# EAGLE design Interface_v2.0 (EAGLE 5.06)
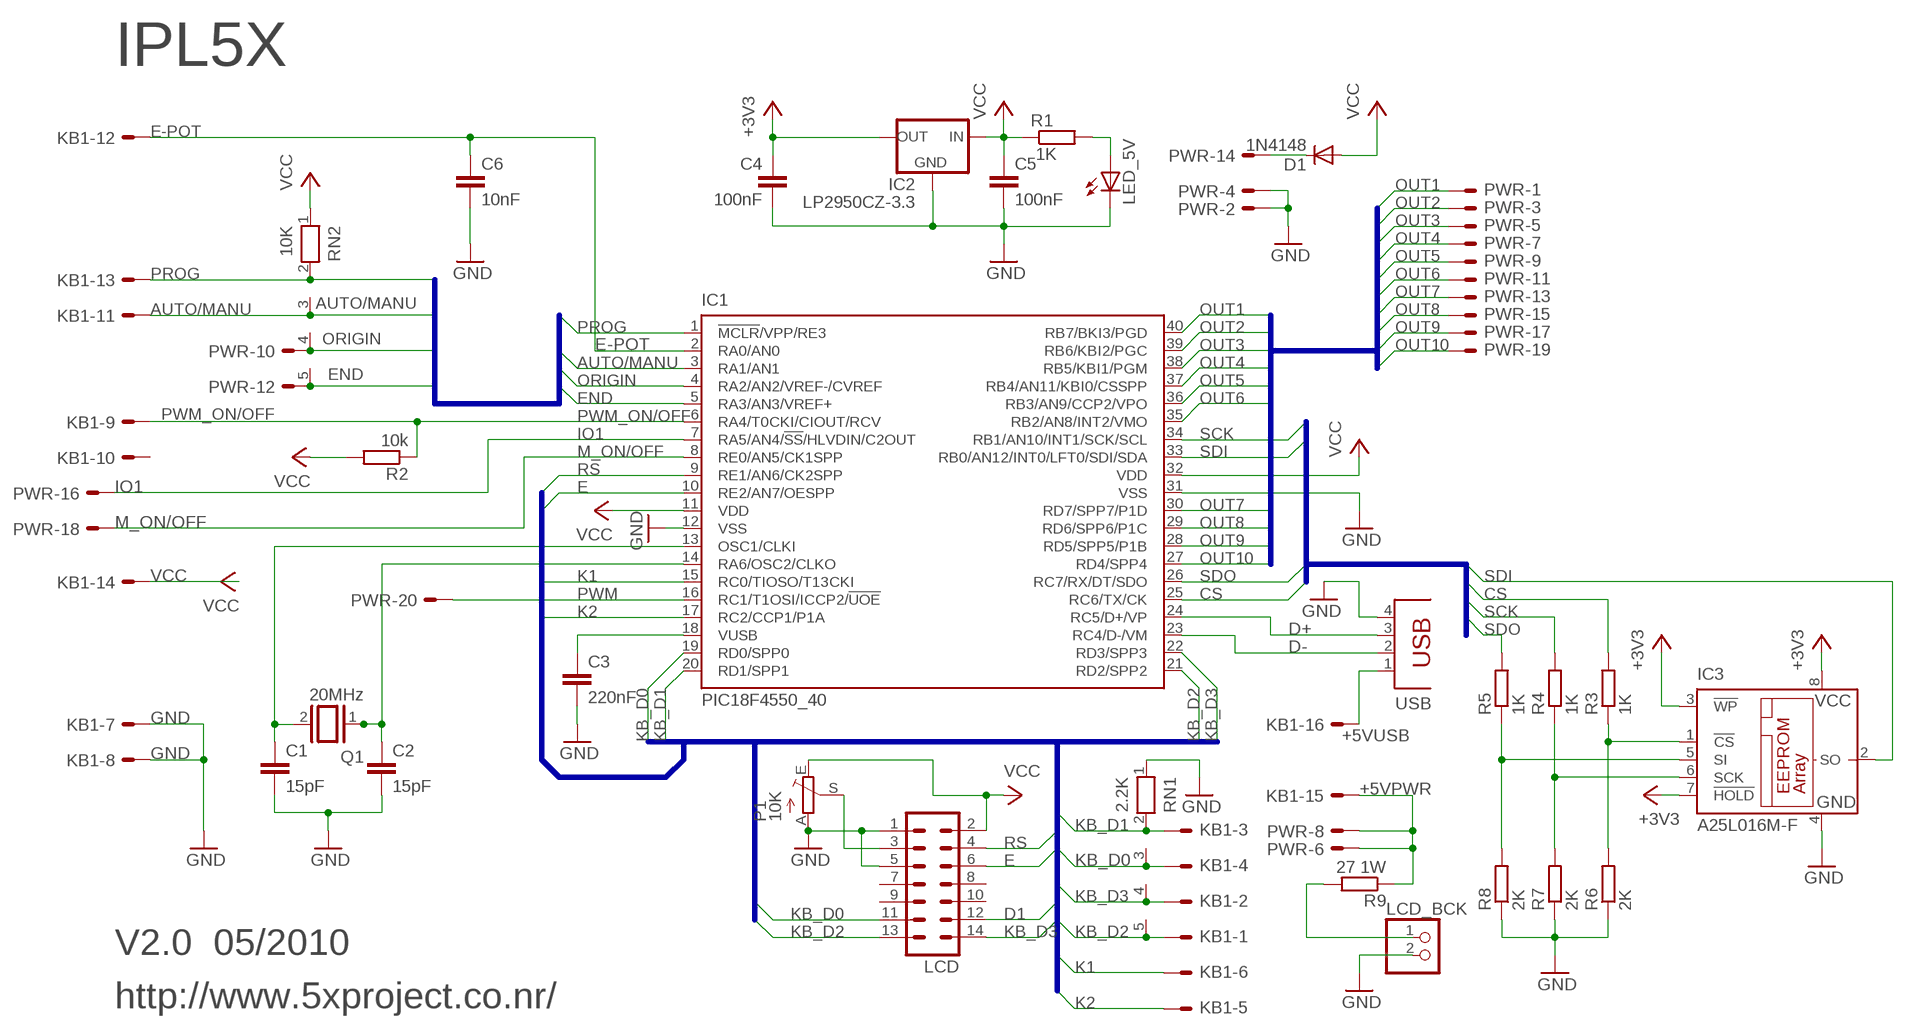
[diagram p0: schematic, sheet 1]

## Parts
C1  15pF  C-EU025-024X044  [C025-024X044]
C2  15pF  C-EU025-024X044  [C025-024X044]
C3  220nF  C-EU050-030X075  [C050-030X075]
C4  100nF  C-EU050-035X075  [C050-035X075]
C5  100nF  C-EU050-030X075  [C050-030X075]
C6  10nF  C-EU050-030X075  [C050-030X075]
D1  1N4148  1N4148DO35-10  [DO35-10]
IC1  PIC18F4550_40  [DIL40]
IC2  LP2950CZ-3.3  LP2950ACZ-3.3  [TO92]
IC3  A25L016M-F  25LC080SN  [SO-08]
KB1  ML16LE  [ML16L]
LCD  ML14L  [ML14L]
LCD_BCK  PINHD-1X2  [1X02]
LED_5V  LED5MM  [LED5MM]
P1  10K  TRIM_EU-LI10  [LI10]
PWR  ML203M20LE  [3M_20L]
Q1  20MHz  XTAL/S  [QS]
R1  1K  R-EU_0207/10  [0207/10]
R2  10k  R-EU_0207/10  [0207/10]
R3  1K  R-EU_0207/10  [0207/10]
R4  1K  R-EU_0207/10  [0207/10]
R5  1K  R-EU_0207/10  [0207/10]
R6  2K  R-EU_0204/7  [0204/7]
R7  2K  R-EU_0204/7  [0204/7]
R8  2K  R-EU_0204/7  [0204/7]
R9  27 1W  R-EU_0309/12  [0309/12]
RN1  2.2K  RN04  [RN-5]
RN2  10K  RN04  [RN-5]
USB  PN61729  [PN61729]

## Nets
+3V3: C4.1 IC2.1(OUT) IC3.3(!WP) IC3.7(!HOLD) IC3.8(VCC)
+5VPWR: KB1.15 PWR.6 PWR.8 R9.1
+5VUSB: KB1.16 USB.1
AUTO/MANU: IC1.3(RA1/AN1) KB1.11 RN2.3
CS: IC1.25(RC6/TX/CK) R3.2
D1: LCD.12
D+: IC1.24(RC5/D+/VP) USB.3
D-: IC1.23(RC4/D-/VM) USB.2
E: IC1.10(RE2/AN7/OESPP) LCD.6
E-POT: C6.1 IC1.2(RA0/AN0) KB1.12
END: IC1.5(RA3/AN3/VREF+) PWR.12 RN2.5
GND: C1.2 C2.2 C3.2 C4.2 C5.2 C6.2 IC1.12(VSS) IC1.31(VSS) IC2.2(GND) IC3.4(GND) KB1.7 KB1.8 LCD.1 LCD.5 LCD_BCK.2 LED_5V.K(C) P1.A PWR.2 PWR.4 R6.1 R7.1 R8.1 RN1.1 USB.4
IO1: IC1.7(RA5/AN4/!SS!/HLVDIN/C2OUT) PWR.16
K1: IC1.15(RC0/TIOSO/T13CKI) KB1.6
K2: IC1.17(RC2/CCP1/P1A) KB1.5
KB_D0: IC1.19(RD0/SPP0) KB1.4 LCD.11 RN1.3
KB_D1: IC1.20(RD1/SPP1) KB1.3 RN1.2
KB_D2: IC1.21(RD2/SPP2) KB1.1 LCD.13 RN1.5
KB_D3: IC1.22(RD3/SPP3) KB1.2 LCD.14 RN1.4
M_ON/OFF: IC1.8(RE0/AN5/CK1SPP) PWR.18
N$1: C2.1 IC1.14(RA6/OSC2/CLKO) Q1.1
N$2: C1.1 IC1.13(OSC1/CLKI) Q1.2
N$6: LED_5V.A R1.2
N$7: C3.1 IC1.18(VUSB)
N$8: IC3.1(!CS) R3.1 R6.2
N$10: IC3.6(SCK) R4.1 R7.2
N$12: LCD_BCK.1 R9.2
N$14: IC3.5(SI) R5.1 R8.2
N$16: LCD.3 P1.S
N$51: D1.C PWR.14
ORIGIN: IC1.4(RA2/AN2/VREF-/CVREF) PWR.10 RN2.4
OUT1: IC1.40(RB7/BKI3/PGD) PWR.1
OUT2: IC1.39(RB6/KBI2/PGC) PWR.3
OUT3: IC1.38(RB5/KBI1/PGM) PWR.5
OUT4: IC1.37(RB4/AN11/KBI0/CSSPP) PWR.7
OUT5: IC1.36(RB3/AN9/CCP2/VPO) PWR.9
OUT6: IC1.35(RB2/AN8/INT2/VMO) PWR.11
OUT7: IC1.30(RD7/SPP7/P1D) PWR.13
OUT8: IC1.29(RD6/SPP6/P1C) PWR.15
OUT9: IC1.28(RD5/SPP5/P1B) PWR.17
OUT10: IC1.27(RD4/SPP4) PWR.19
PROG: IC1.1(!MCLR!/VPP/RE3) KB1.13 RN2.2
PWM: IC1.16(RC1/T1OSI/ICCP2/!UOE) PWR.20
PWM_ON/OFF: IC1.6(RA4/T0CKI/CIOUT/RCV) KB1.9 R2.1
RS: IC1.9(RE1/AN6/CK2SPP) LCD.4
SCK: IC1.34(RB1/AN10/INT1/SCK/SCL) R4.2
SDI: IC1.33(RB0/AN12/INT0/LFT0/SDI/SDA) IC3.2(SO)
SDO: IC1.26(RC7/RX/DT/SDO) R5.2
VCC: C5.1 D1.A IC1.11(VDD) IC1.32(VDD) IC2.3(IN) KB1.14 LCD.2 P1.E R1.1 R2.2 RN2.1
Unconnected: KB1.10 LCD.7 LCD.8 LCD.9 LCD.10

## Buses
OUT1,OUT2,OUT3,OUT4,OUT5,OUT6,OUT7,OUT8,OUT9,OUT10
SDI,SDO,SCK,CS
PROG,AUTO/MANU,ORIGIN,END,M_ON/OFF
D0,D1,D2,D3,E,RS,K1,K2

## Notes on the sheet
- IPL5X
- V2.0  05/2010
- http://www.5xproject.co.nr/

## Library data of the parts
C1-C6 = rcl:C-EU: CAPACITOR, European symbol
D1 = diode:1N4148: DIODE
IC1 = microchip:PIC18F4*_40: USB Microcontrollers with nanoWatt Technology High-Performance, Enhanced Flash, 28/40/44-Pin, Source: http://ww1.microchip.com/downloads/en/devicedoc/39632c.pdf
IC2 = v-reg:LP2950?*: Source: http://cache.national.com/ds/LP/LP2950.pdf
IC3 = microchip:25*: Serial EEPROM 4 K, SPI bus
KB1 = con-harting-ml:ML16?E: HARTING
LCD = con-harting-ml:ML14: HARTING
LCD_BCK = pinhead:PINHD-1X2: PIN HEADER
LED_5V = led:LED: LED
P1 = pot:TRIM_EU-: POTENTIOMETER
PWR = con-harting-ml:ML20?E: HARTING
Q1 = special:XTAL/S: CRYSTAL
R1-R9 = rcl:R-EU_: RESISTOR, European symbol
RN1 RN2 = resistor-net:RN04: RESISTOR NETWORK
USB = con-berg:PN61729: BERG USB connector

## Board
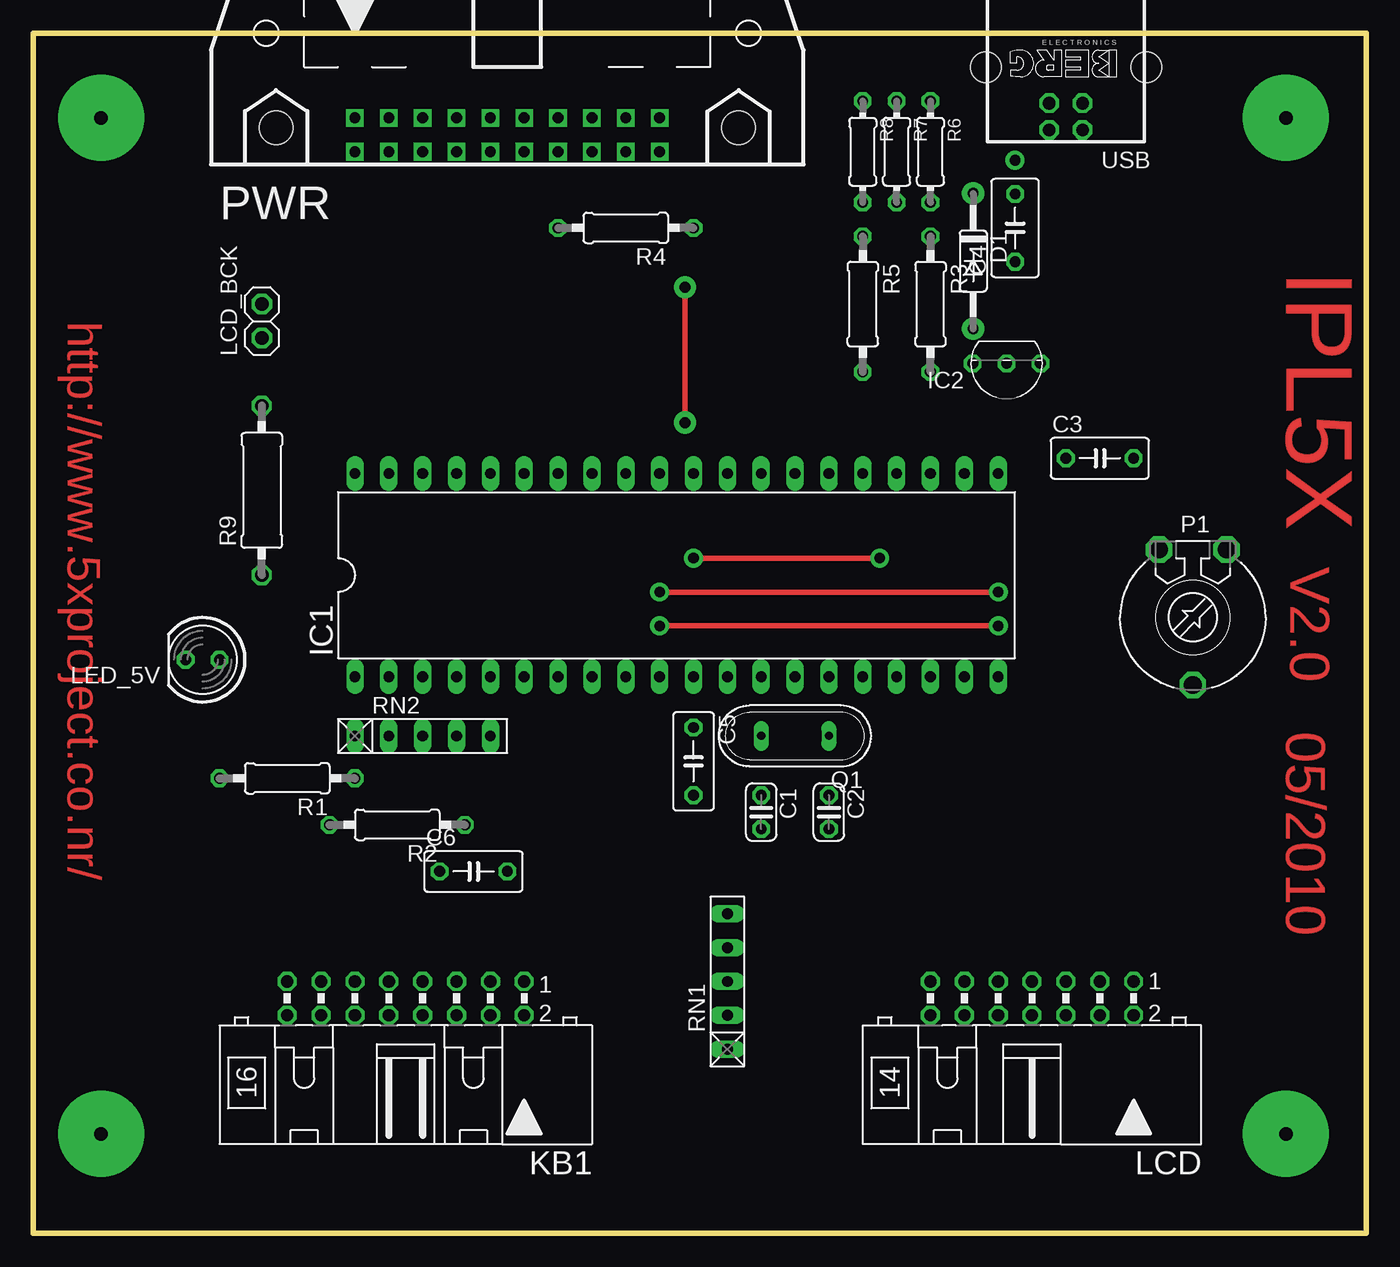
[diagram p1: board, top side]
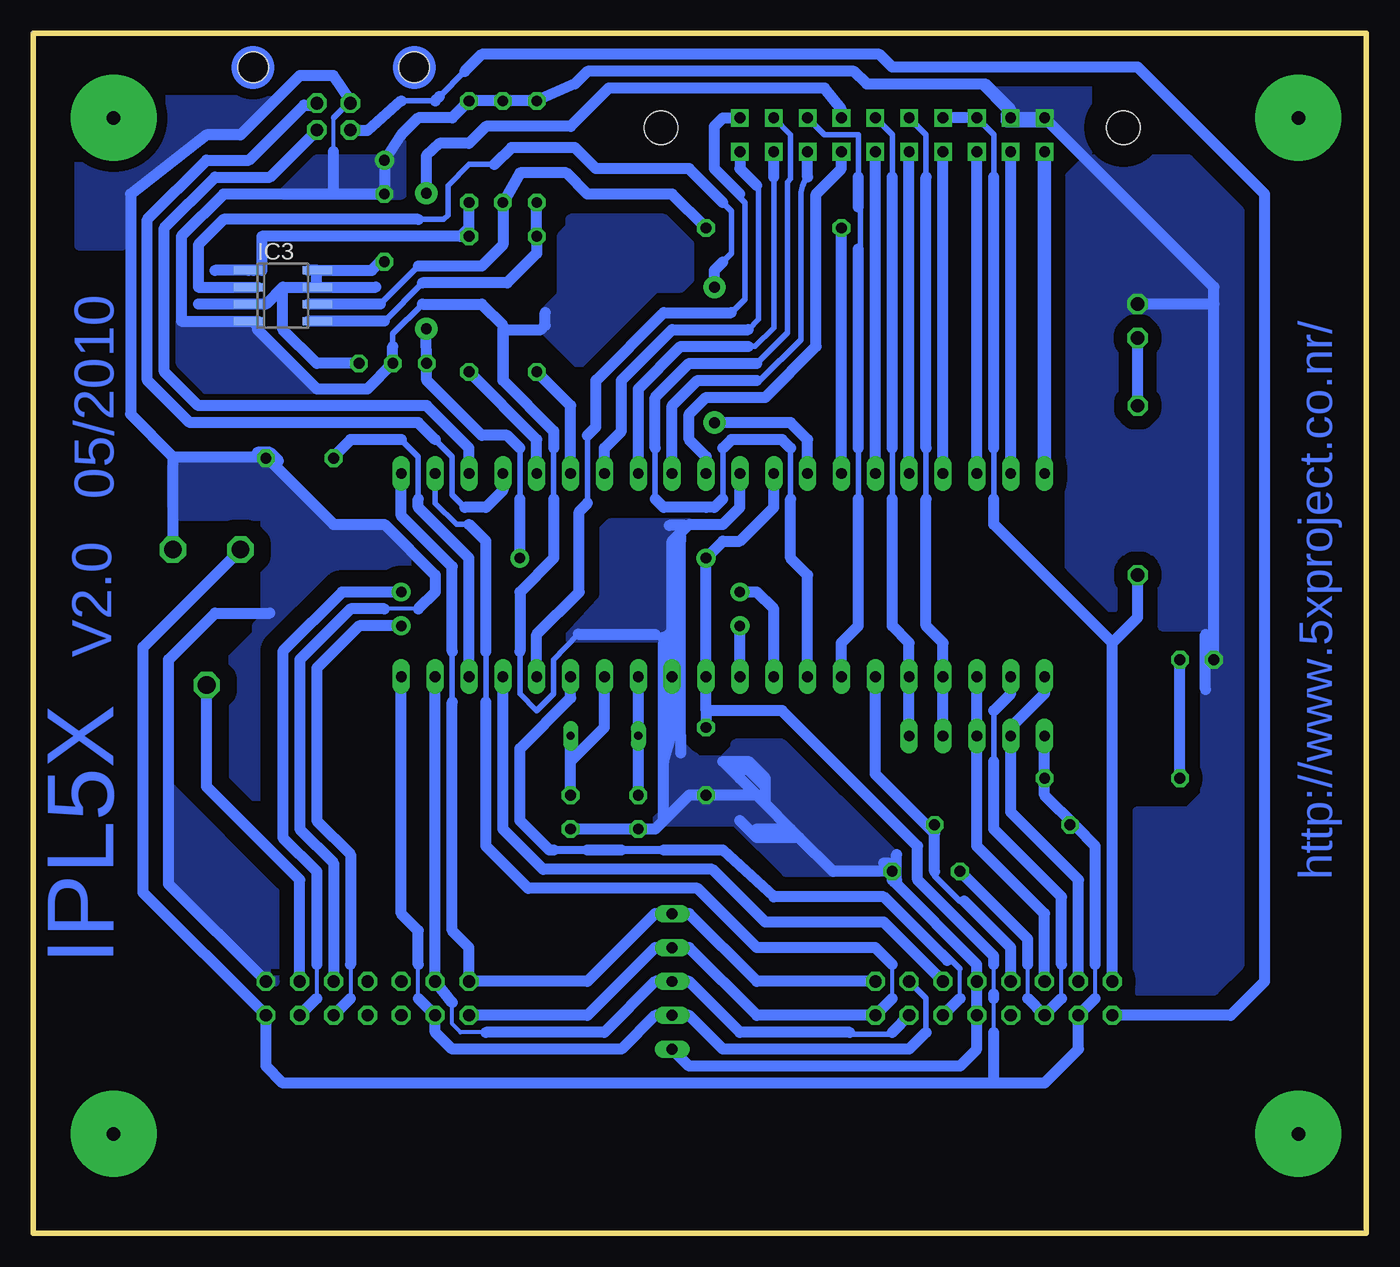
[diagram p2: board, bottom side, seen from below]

Size 100 x 90 mm. Coordinates in mm from the lower left corner, seen from the top.
Outline: 0,0 100,0 100,90 0,90 0,0
Copper layers (1*16): Top 0.035mm / dielectric 1.5mm / Bottom 0.035mm
Design rules "default *": minimum track width 10mil, minimum drill 24mil, track to track 15mil, track to pad 15mil, pad to pad 15mil, via to via 15mil, smd to smd 8mil, copper to edge 40mil, drill to drill 8mil, minimum pad ring 10mil, minimum via ring 8mil, stop-mask expansion 4mil, vias tented up to drill 0mil, thermal gap 10mil

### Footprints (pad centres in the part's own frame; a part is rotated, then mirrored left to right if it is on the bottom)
C025-024X044 = drill 0.813 octagon: 1 -1.27,0; 2 1.27,0
C050-030X075 = drill 0.813 octagon: 1 -2.54,0; 2 2.54,0
C050-035X075 = drill 0.813 octagon: 1 -2.54,0; 2 2.54,0
DO35-10 = drill 0.813 pad 1.676 round: A 5.08,0; C -5.08,0
DIL40 = drill 0.813 long: 1 -24.13,-7.62; 2 -21.59,-7.62; 3 -19.05,-7.62; 4 -16.51,-7.62; 5 -13.97,-7.62; 6 -11.43,-7.62; 7 -8.89,-7.62; 8 -6.35,-7.62; 9 -3.81,-7.62; 10 -1.27,-7.62; 11 1.27,-7.62; 12 3.81,-7.62; 13 6.35,-7.62; 14 8.89,-7.62; 15 11.43,-7.62; 16 13.97,-7.62; 17 16.51,-7.62; 18 19.05,-7.62; 19 21.59,-7.62; 20 24.13,-7.62; 21 24.13,7.62; 22 21.59,7.62; 23 19.05,7.62; 24 16.51,7.62; 25 13.97,7.62; 26 11.43,7.62; 27 8.89,7.62; 28 6.35,7.62; 29 3.81,7.62; 30 1.27,7.62; 31 -1.27,7.62; 32 -3.81,7.62; 33 -6.35,7.62; 34 -8.89,7.62; 35 -11.43,7.62; 36 -13.97,7.62; 37 -16.51,7.62; 38 -19.05,7.62; 39 -21.59,7.62; 40 -24.13,7.62
TO92 = drill 0.813 octagon: 1 -2.54,0; 2 0,0; 3 2.54,0
SO-08 = smd 0.6 x 2.2: 1 -1.905,-2.6; 2 -0.635,-2.6; 3 0.635,-2.6; 4 1.905,-2.6; 5 1.905,2.6; 6 0.635,2.6; 7 -0.635,2.6; 8 -1.905,2.6
ML16L = drill 0.914 octagon: 1 -8.89,-1.27; 2 -8.89,1.27; 3 -6.35,-1.27; 4 -6.35,1.27; 5 -3.81,-1.27; 6 -3.81,1.27; 7 -1.27,-1.27; 8 -1.27,1.27; 9 1.27,-1.27; 10 1.27,1.27; 11 3.81,-1.27; 12 3.81,1.27; 13 6.35,-1.27; 14 6.35,1.27; 15 8.89,-1.27; 16 8.89,1.27
ML14L = drill 0.914 octagon: 1 -7.62,-1.27; 2 -7.62,1.27; 3 -5.08,-1.27; 4 -5.08,1.27; 5 -2.54,-1.27; 6 -2.54,1.27; 7 0,-1.27; 8 0,1.27; 9 2.54,-1.27; 10 2.54,1.27; 11 5.08,-1.27; 12 5.08,1.27; 13 7.62,-1.27; 14 7.62,1.27
1X02 = drill 1.016 octagon: 1 -1.27,0; 2 1.27,0
LED5MM = drill 0.813 octagon: A -1.27,0; K 1.27,0
LI10 = drill 1.321 octagon: A -2.54,-5.08; E 2.54,-5.08; S 0,5.08
3M_20L = drill 0.813 square: 1 -11.43,-5.08; 2 -11.43,-2.54; 3 -8.89,-5.08; 4 -8.89,-2.54; 5 -6.35,-5.08; 6 -6.35,-2.54; 7 -3.81,-5.08; 8 -3.81,-2.54; 9 -1.27,-5.08; 10 -1.27,-2.54; 11 1.27,-5.08; 12 1.27,-2.54; 13 3.81,-5.08; 14 3.81,-2.54; 15 6.35,-5.08; 16 6.35,-2.54; 17 8.89,-5.08; 18 8.89,-2.54; 19 11.43,-5.08; 20 11.43,-2.54 | hole 2.54: -17.348,-3.277; 17.348,-3.277
QS = drill 0.61 long: 1 -2.54,0; 2 2.54,0
0207/10 = drill 0.813 octagon: 1 -5.08,0; 2 5.08,0
0204/7 = drill 0.813 octagon: 1 -3.81,0; 2 3.81,0
0309/12 = drill 1 octagon: 1 -6.35,0; 2 6.35,0
RN-5 = drill 0.813 long: 1 -5.08,0; 2 -2.54,0; 3 0,0; 4 2.54,0; 5 5.08,0
PN61729 = drill 0.95 octagon: 1 1.25,4.71; 2 -1.25,4.71; 3 -1.25,2.71; 4 1.25,2.71 | hole 2.3: -6.02,0; 6.02,0

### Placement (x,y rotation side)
C1  54.61,31.59 270 top
C2  59.69,31.59 270 top
C3  80.01,58.13 0 top
C4  73.66,75.41 90 top
C5  49.53,35.4 270 top
C6  33.02,27.14 0 top
D1  70.52,72.92 270 top
IC1  48.26,49.37 0 top
IC2  73.03,65.25 180 top
IC3  81.28,70.33 270 bottom
KB1  27.94,17.62 180 top
LCD  74.93,17.62 180 top
LCD_BCK  17.14,68.42 90 top
LED_5V  12.7,43.02 180 top
P1  87,46.2 180 top
PWR  35.56,86.2 0 top
Q1  57.15,37.3 180 top
R1  19.05,34.13 180 top
R2  27.3,30.64 180 top
R3  67.31,69.69 270 top
R4  44.45,75.41 180 top
R5  62.23,69.69 270 top
R6  67.31,81.12 270 top
R7  64.77,81.12 270 top
R8  62.23,81.12 270 top
R9  17.14,55.72 90 top
RN1  52.07,18.89 90 top
RN2  29.21,37.3 0 top
USB  77.47,87.47 180 top

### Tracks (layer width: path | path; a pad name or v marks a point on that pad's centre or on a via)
+3V3
  Bottom 0.406: IC3.8 IC3.7 78.74,70.96 | 81.28,70.96 81.6,70.64 | 81.6,70.64 82.55,69.69 | 87.63,69.69 IC3.3 | 81.28,67.78 81.28,70.33 81.6,70.64
  Bottom 0.813: C4.1 73.98,72.87 74.61,72.23 IC3.8 79.38,72.23 | 78.74,70.96 78.74,72.23 | 81.28,70.96 78.74,70.96 | 81.28,70.96 81.28,67.78 78.74,65.25 IC2.1 | 81.28,70.96 82.55,69.69 87.63,69.69 | 78.74,70.96 74.3,70.96
+5VPWR
  Bottom 0.406: PWR.6 27.94,82.39 27.94,79.22 | 27.94,53.18 27.94,54.45 | 27.94,55.09 27.94,58.9
  Bottom 0.813: PWR.6 PWR.8 | 27.94,58.9 27.94,79.22 | 27.94,54.45 27.94,55.09 27.94,53.18 19.05,44.29 | 19.05,44.29 17.14,46.2 R9.1 | KB1.15 19.05,44.29
+5VUSB
  Bottom 0.406: 69.85,84.93 72.39,84.93 | 67.63,87.15 69.53,85.25 | USB.1 76.17,82.76 76.17,82.71
  Bottom 0.813: 76.17,82.71 74.93,82.71 72.39,84.93 | KB1.16 10.16,16.35 7.62,18.89 7.62,77.94 17.14,87.47 35.56,87.47 36.51,88.42 66.36,88.42 67.63,87.15 | 69.53,85.25 69.85,84.93
AUTO/MANU
  Bottom 0.254: RN2.3 IC1.3
  Bottom 0.406: 29.21,29.05 RN2.3
  Bottom 0.813: IC1.3 29.21,29.05 24.13,23.97 KB1.11
CS
  Bottom 0.813: IC1.25 62.23,59.53 R3.2
D1
  Bottom 0.305: 71.12,17.62 71.12,20.16 | 33.02,15.08 33.02,17.62
  Bottom 0.813: 71.12,17.62 LCD.12 69.85,15.08 68.58,13.81 55.88,13.81 53.34,16.35 50.8,16.35 48.26,13.81 34.29,13.81 33.02,15.08 | 72.39,23.97 71.12,22.7 71.12,20.16
D+
  Bottom 0.406: 69.85,59.53 68.58,58.26 68.58,55.4 67.63,54.45 | 83.82,80.48 83.63,80.48 79.69,84.61 USB.3
  Bottom 0.813: 78.74,84.61 79.69,84.61 83.82,80.48 87,80.48 91.44,76.04 91.44,63.98 88.27,60.8 71.12,60.8 69.85,59.53 | IC1.24 64.77,55.72 66.04,54.45 67.63,54.45
D-
  Bottom 0.406: USB.2 81.89,79.23 82.23,79.22
  Bottom 0.813: IC1.23 67.31,58.9 70.48,62.07 87.63,62.07 90.17,64.61 90.17,75.41 86.36,79.22 82.23,79.22 78.74,82.71
E  (via drill 0.8 pad 1.42)
  Top 0.406: v46.99,45.56 v72.39,45.56
  Bottom 0.305: 76.2,20.16 76.2,17.62
  Bottom 0.406: IC1.10 v46.99,45.56
  Bottom 0.813: 76.2,17.62 LCD.6 | IC1.10 v46.99,45.56 | v72.39,45.56 75.56,45.56 78.74,42.38 78.74,30.95 76.2,28.41 76.2,20.16
E-POT
  Bottom 0.305: 22.86,17.62 22.86,20.16 | 25.4,17.62 25.4,20.16
  Bottom 0.406: 27.94,35.4 27.94,39.21
  Bottom 0.813: 22.86,17.62 KB1.12 25.4,17.62 | IC1.2 26.67,40.48 27.94,39.21 | 27.94,35.4 27.94,30.32 22.86,25.24 22.86,20.16 | 25.4,20.16 25.4,22.06 C6.1
END
  Bottom 0.254: RN2.5 IC1.5 34.29,44.29
  Bottom 0.406: PWR.12 35.56,82.39 35.56,79.22 | 35.56,55.09 35.56,58.9
  Bottom 0.813: 35.56,58.9 35.56,79.22 | 35.56,55.09 35.56,45.56 34.29,44.29 RN2.5
GND  (via drill 0.8 pad 1.42)
  Bottom 0.254: PWR.2 PWR.4 26.99,83.98 29.21,86.2 37.47,86.2 | R8.1 R7.1 R6.1 | 82.55,58.26 C3.2 | IC2.2 73.66,64.61 73.61,64.56
  Bottom 0.305: 77.47,81.12 77.47,83.66 | 71.12,46.83 73.66,46.83
  Bottom 0.406: IC2.2 73.61,64.56 74.55,63.45 78.47,63.34 80.01,64.61 83.19,67.78 83.82,68.42 IC3.4 83.19,68.42 | USB.4 76.2,84.78 76.2,84.93 77.47,83.66 | 77.47,53.18 82.42,58.13 C3.2 | KB1.7 KB1.8 | 63.5,43.66 63.5,40.48 62.23,39.21 60.96,40.48 60.96,43.02 59.13,44.95 | 60.96,58.9 60.96,55.09 | 52.7,35.4 52.7,38.58 52.7,44.29 | 52.07,39.21 IC1.12 | 53.36,44.7 53.36,44.92 | 53.36,44.7 53.46,44.7 | 52.77,44.7 53.36,44.7 | 52.07,51.91 52.07,51.89 | 70.8,69.69 73.03,67.47 73.03,66.52 | LED_5V.K 12.06,43.02 12.06,43.34 | 35.24,26.51 35.4,26.51 35.4,26.35 | 82.23,58.58 82.55,58.58 82.55,58.26
  Bottom 0.813: RN1.1 50.8,12.54 30.48,12.54 29.21,13.81 KB1.7 29.21,20.16 35.4,26.35 35.56,26.51 C6.2 40.01,27.14 42.55,29.68 | 52.7,30.95 50.8,32.86 C5.2 45.72,32.86 | IC1.31 46.99,54.45 48.26,53.18 50.8,53.18 52.07,51.91 52.07,45.15 | IC1.12 52.07,45.15 | 59.13,44.95 53.34,44.92 | 60.96,55.09 60.96,50.64 63.5,48.1 63.5,43.66 | 60.96,58.9 60.96,60.16 64.77,63.98 | 73.03,66.52 IC2.2 74.93,63.34 78.74,63.34 83.19,67.78 83.19,68.42 88.9,68.42 88.9,74.77 85.72,77.94 77.47,77.94 | 71.12,46.83 69.85,48.1 69.85,49.37 73.66,53.18 77.47,53.18 82.55,58.26 89.53,58.26 | 73.66,46.83 76.2,46.83 80.01,43.02 80.01,30.32 77.47,27.78 LCD.5 | 77.47,77.94 C4.2 v73.66,80.48 72.39,82.39 71.12,83.66 68.58,83.66 R6.1 R8.1 59.37,86.2 58.42,87.15 38.42,87.15 37.47,86.2 28.57,86.2 26.67,84.3 PWR.4 PWR.2 23.81,83.34 | 77.47,77.94 77.47,81.12 | 76.2,84.93 77.47,86.83 80.01,86.83 84.45,82.39 87,82.39 92.71,77.94 92.71,61.44 89.53,58.26 | 23.81,83.34 11.43,70.96 11.43,69.69 | 11.43,69.69 LCD_BCK.2 | LED_5V.K 11.43,69.69 | 89.53,58.26 P1.A | 52.7,30.95 52.7,35.4 | 52.7,30.95 53.34,30.32 C1.2 C2.2 | 52.7,38.58 51.44,37.3 | 51.44,37.3 51.44,52.23 52.07,38.58 52.07,39.21 | 51.44,37.3 51.44,36.03 | 64.77,63.98 64.77,67.78 61.91,67.78 61.59,68.1 61.59,69.06 | 45.72,32.86 46.99,34.13 | 43.18,30.32 45.09,32.23 | 45.72,32.86 48.26,35.4 46.35,35.4 45.09,34.13 45.09,33.5 | 45.09,32.23 45.72,32.86 | 45.09,32.23 45.09,33.5 | 46.99,30.95 45.72,29.68 42.55,29.68 | 42.55,29.68 43.18,30.32 | 43.18,30.32 45.72,30.32 | 46.99,34.77 46.35,34.77 45.09,33.5 | 52.77,44.7 52.52,44.7 52.07,45.15 | 51.09,53.1 52.3,53.1 | 64.77,63.98 64.77,68.1 66.36,69.69 70.8,69.69
  Bottom 0.813: 52.7,35.4 52.7,44.29 | 52.7,35.4 52.07,37.62 | LCD.1 89.85,26.19 89.85,43.02 86.36,46.51 82.23,46.51 | 12.06,40.8 12.06,43.34 12.06,44.92 | 35.24,28.41 35.24,26.51 36.2,27.78 35.88,27.78 | 83.19,58.58 82.23,58.58 81.6,57.94 | 23.81,83.34 26.99,83.34 26.99,83.98
  pour Bottom (isolate 1.016, no thermals): 11.43,43.66 11.43,41.11 12.06,40.48 12.06,32.86 13.34,31.59 17.14,31.59 17.14,18.26 11.43,18.26 9.53,20.16 9.53,76.67 13.34,80.48 20.95,80.48 22.23,79.22 22.23,49.37 19.68,46.83 19.05,46.83 19.05,50.64 18.41,51.27 15.88,51.27 15.24,50.64 15.24,45.56 12.06,45.56
  pour Bottom (isolate 1.016, no thermals): 20.95,80.48 20.95,86.2 21.59,86.2 28.57,86.2 26.04,83.66 24.13,83.66
  pour Bottom (no thermals): 72.39,81.75 73.66,80.48 77.47,80.48 78.74,80.48 81.28,77.94 72.39,77.94 72.39,81.12
  pour Bottom (no thermals): 78.74,63.34 87,63.34 88.9,65.25 88.9,68.42 83.82,68.42
  pour Bottom (isolate 0.813, no thermals): 81.92,84.93 92.71,84.93 96.52,81.12 96.52,74.14 93.34,74.14 92.71,77.94 87,82.39 84.45,82.39
  pour Bottom (isolate 1.27, no thermals): 71.12,49.37 78.11,49.37 83.19,44.29 82.55,43.66 82.55,31.59 85.09,34.13 85.09,43.02 83.19,44.92 83.19,45.56 82.55,46.2 82.55,53.81 88.9,53.81 89.53,54.45 89.53,57.62 83.19,57.62 82.55,58.26 82.55,57.62 78.11,53.18 73.66,53.18
  pour Bottom (isolate 1.27, no thermals): 53.34,30.95 43.81,30.95 48.26,35.4 50.16,35.4 51.44,36.67 53.34,37.94
  pour Bottom (no thermals): 50.8,74.14 52.7,76.04 59.69,76.04 59.69,75.41 60.33,74.77 60.33,70.33 61.59,69.06 61.59,67.78 59.05,65.25 53.34,70.96 51.44,70.96 50.8,71.59
  pour Bottom: 46.99,36.67 48.26,35.4 48.26,31.59 44.45,31.59 45.72,32.86 46.99,34.13
  pour Bottom: 50.74,53.2 56.71,53.2 57.16,52.75 57.16,47.72 57.11,47.67 59.79,44.73 52.2,44.72 52.15,44.76 52.15,52.01 52.06,52.11
  pour Bottom: 35.56,27.14 35.56,28.41 43.81,36.67 47.31,36.67 47.31,30.95 43.5,27.14
  pour Bottom: 81.92,25.56 89.85,33.5 89.85,26.19 82.55,18.89 81.92,18.89
IO1
  Bottom 0.254: 38.1,73.82 38.1,73.98 37.94,73.5 | 37.94,77.15 37.94,76.83 38.1,76.99
  Bottom 0.406: 38.1,55.09 38.1,58.9 | 37.94,73.5 37.94,77.15 | 38.1,79.22 38.1,82.39 40.64,82.39 PWR.16
  Bottom 0.813: 38.1,76.99 38.1,79.22 | 38.1,58.9 38.1,73.82 | 38.1,55.09 38.1,45.56 39.37,44.29 IC1.7
K1
  Bottom 0.305: 30.48,17.62 30.48,19.84
  Bottom 0.406: 30.48,19.84 31.75,21.11 31.43,20.48
  Bottom 0.61: 58.42,28.73 60.96,28.73 | 52.7,28.73 55.88,28.73
  Bottom 0.813: KB1.6 30.48,17.62 | 31.43,20.48 36.2,25.24 44.45,25.24 48.26,28.73 52.7,28.73 | 55.88,28.73 58.42,28.73 | 60.96,28.73 61.28,28.73 63.5,30.95 63.5,36.35 59.69,40.16 IC1.15
K2
  Bottom 0.813: KB1.5 36.2,23.34 45.09,23.34 49.05,27.3 61.75,27.3 64.77,30.32 IC1.17
KB_D0
  Bottom 0.305: 68.58,17.3 68.58,15.71 67.94,15.08 66.04,15.08 | 35.56,15.08 35.72,15.08 35.72,14.92 | 38.58,14.92 38.58,15.08 38.73,15.08
  Bottom 0.406: 35.72,14.92 38.58,14.92
  Bottom 0.813: 68.58,17.3 LCD.11 IC1.19 | 66.04,15.08 57.15,15.08 53.34,18.89 RN1.3 50.8,18.89 46.99,15.08 38.73,15.08 | KB1.4 35.56,15.08
KB_D1
  Bottom 0.305: 71.12,17.62 71.12,22.7
  Bottom 0.406: KB1.3 33.02,17.62 33.02,15.08 34.29,13.81 48.26,13.81 50.8,16.35 RN1.2 53.34,16.35 55.88,13.81 68.58,13.81 69.85,15.08 69.85,16.35 71.12,17.62 | 71.12,22.7 72.39,23.97
  Bottom 0.813: 72.39,23.97 IC1.20
KB_D2
  Bottom 0.406: 68.58,44.29 68.58,43.66 68.58,39.84
  Bottom 0.813: KB1.1 45.72,18.89 50.8,23.97 RN1.5 53.34,23.97 58.42,18.89 LCD.13 67.31,21.43 68.58,22.7 68.58,39.84 | 68.58,43.66 68.58,50.01 72.39,53.81 IC1.21
KB_D3
  Bottom 0.305: 35.56,17.62 35.56,20.16
  Bottom 0.406: IC1.22 69.85,54.77 68.26,53.18 67.31,53.18 | 66.04,39.84 66.04,43.66
  Bottom 0.813: 35.56,17.62 KB1.2 45.72,16.35 50.8,21.43 RN1.4 53.34,21.43 58.42,16.35 LCD.14 | 66.04,43.66 66.04,51.91 67.31,53.18 | 66.04,39.84 66.04,29.05 62.87,25.88 50.16,25.88 45.72,21.43 36.83,21.43 35.56,20.16
M_ON/OFF
  Bottom 0.406: PWR.18 43.18,82.39 43.18,79.09 43.43,78.83 43.43,67.53 45.59,65.37 50.67,65.37 50.8,65.25 | 49.53,54.45 52.7,54.45 | 48.26,58.9 48.26,55.09 | 43.18,55.09 43.18,58.9 | 53.34,55.09 53.34,58.9
  Bottom 0.813: 48.26,58.9 47.62,59.53 43.81,59.53 43.18,58.9 | 43.18,55.09 43.18,50.64 41.91,49.37 IC1.8 | 53.34,58.9 53.34,62.7 50.8,65.25 45.72,65.25 | 48.9,54.45 49.53,54.45 | 53.34,55.09 52.7,54.45 48.9,54.45 | 48.26,55.09 48.9,54.45
N$1
  Bottom 0.406: C2.1 59.69,35.4
  Bottom 0.813: IC1.14 57.15,37.94 59.69,35.4 Q1.1 C2.1
N$2
  Bottom 0.254: Q1.2 IC1.13
  Bottom 0.406: C1.1 Q1.2
  Bottom 0.813: C1.1 IC1.13
N$4  (via drill 1 pad 6.45)
  other vias: 5.08,83.66
N$6
  Bottom 0.254: R1.2 LED_5V.A
  Bottom 0.813: R1.2 LED_5V.A
N$7
  Bottom 0.406: 72.39,59.53 71.12,58.26 71.12,55.09 | 77.47,58.26 C3.1
  Bottom 0.813: IC1.18 67.31,50.64 71.12,54.45 71.12,55.09 | 72.39,59.53 76.2,59.53 77.47,58.26
N$8
  Bottom 0.406: 67.31,75.41 R3.1 R6.2
  Bottom 0.813: 67.31,75.41 67.94,74.77 82.87,74.77 82.87,72.23 83.5,72.23 IC3.1 86.36,72.23 | R3.1 R6.2
N$9  (via drill 1 pad 6.45)
  other vias: 93.98,83.66
N$10
  Bottom 0.406: 79.38,69.69 IC3.6 78.74,69.69 | 71.12,72.55 73.98,69.69
  Bottom 0.813: R4.1 52.07,77.94 58.42,77.94 60.01,79.53 63.5,79.53 R7.2 64.77,74.14 66.36,72.55 71.12,72.55 | 73.98,69.69 79.38,69.69
N$12
  Bottom 0.406: R9.2 LCD_BCK.1
  Bottom 0.813: R9.2 LCD_BCK.1
N$13  (via drill 1 pad 6.45)
  other vias: 5.08,7.46
N$14
  Bottom 0.406: 70.8,71.28 73.66,68.42
  Bottom 0.813: R8.2 R5.1 62.23,73.5 64.45,71.28 70.8,71.28 | 73.66,68.42 IC3.5 79.38,68.42
N$15  (via drill 1 pad 6.45)
  other vias: 93.98,7.46
N$16
  Bottom 0.254: LCD.3 80.01,23.97
  Bottom 0.406: 80.01,23.97 80.01,26.51
  Bottom 0.813: P1.S 87,33.5 80.01,26.51 LCD.3
N$51
  Bottom 0.813: PWR.14 39.37,84.3 40.64,85.88 56.83,85.88 59.69,83.03 66.04,83.03 67.31,81.75 69.53,81.75 70.52,80.81 D1.C
ORIGIN
  Bottom 0.254: RN2.4 IC1.4 | IC1.4 31.75,43.02 | IC1.4 31.75,39.84 | IC1.4 31.75,44.29
  Bottom 0.406: PWR.10 33.02,82.39 33.02,79.22 | 33.02,55.09 33.02,58.9
  Bottom 0.813: 33.02,58.9 33.02,79.22 | 33.02,55.09 33.02,45.56 31.75,44.29 RN2.4
OUT1
  Bottom 1.016: IC1.40 PWR.1
OUT2
  Bottom 0.813: IC1.39 PWR.3
OUT3
  Bottom 0.813: IC1.38 PWR.5
OUT4
  Bottom 0.813: IC1.37 PWR.7
OUT5
  Bottom 0.813: IC1.36 PWR.9
OUT6
  Bottom 0.813: IC1.35 PWR.11
OUT7
  Bottom 0.813: PWR.13 39.37,79.85 41.27,77.94 41.27,66.52 45.09,62.7 49.53,62.7 50.8,61.44 50.8,59.53 49.53,58.26 IC1.30
OUT8
  Bottom 0.406: 41.91,79.22 42.04,79.09 42.04,79.15 41.97,79.37 42.29,78.52 42.42,78.07 42.42,67.02 45.47,63.98 45.72,63.98
  Bottom 0.813: IC1.29 52.07,62.07 50.16,63.98 45.72,63.98 | 41.91,79.22 PWR.15
OUT9
  Bottom 0.406: 44.45,79.22 44.45,67.91 45.85,66.52 46.35,66.52
  Bottom 0.813: IC1.28 54.61,63.34 51.44,66.52 46.35,66.52 | 44.45,79.22 PWR.17
OUT10
  Bottom 0.406: PWR.19 46.99,79.98 45.59,78.58 45.59,68.55 46.35,67.78
  Bottom 0.813: 46.35,67.78 52.07,67.78 55.88,63.98 55.88,60.16 57.15,58.9 IC1.27 | PWR.19 46.99,79.85 45.72,78.58
PROG
  Bottom 0.406: 26.67,37.62 RN2.2 26.67,31.59
  Bottom 0.813: KB1.13 21.59,26.51 26.67,31.59 26.67,37.62 26.67,37.94 24.13,40.48 IC1.1
PWM
  Bottom 0.406: 48.9,79.85 48.9,79.6 46.61,77.31 46.61,70.07 47.62,69.06 47.75,68.93 52.83,68.93 | 57.78,63.98 52.7,69.06 | 58.42,54.77 58.42,59.85
  Bottom 0.813: 52.83,68.93 57.72,64.03 | PWR.20 48.26,83.66 48.9,83.03 48.9,79.85 46.99,77.94 | 52.7,69.06 47.62,69.06 | 57.78,63.98 57.78,60.48 58.42,59.85 | 58.42,54.77 59.05,54.13 59.05,48.1 62.23,44.92 IC1.16
PWM_ON/OFF
  Bottom 0.406: 30.16,24.92 30.48,24.92 32.38,26.83 32.38,27.14 | R2.1 32.7,30.64 32.7,30.32
  Bottom 0.813: IC1.6 36.83,34.45 32.7,30.32 32.38,30 32.38,27.14 | KB1.9 26.67,21.43 30.16,24.92
RS  (via drill 0.8 pad 1.42)
  Top 0.406: v46.99,48.1 v72.39,48.1
  Bottom 0.305: 78.74,20.16 78.74,17.62
  Bottom 0.813: v46.99,48.1 45.72,48.1 44.45,46.83 IC1.9 | v72.39,48.1 76.83,48.1 81.28,43.66 81.28,29.68 78.74,27.14 78.74,20.16 | 78.74,17.62 LCD.4
SCK
  Bottom 0.813: IC1.34 R4.2
SDI  (via drill 0.8 pad 1.68)
  Top 0.406: v48.9,60.8 v48.9,70.96
  Bottom 0.406: 83.19,70.96 IC3.2 | 65.41,80.17 67.31,80.17 68.9,78.58 68.9,76.36 69.22,76.04 71.12,76.04 | 48.26,77.31 47.62,76.67 47.62,73.5 48.26,72.87
  Bottom 0.813: IC1.33 41.91,59.53 43.18,60.8 v48.9,60.8 | 71.12,76.04 85.72,76.04 87.63,74.14 87.63,70.96 83.19,70.96 | v48.9,70.96 48.9,72.23 48.26,72.87 | 48.26,77.31 50.8,79.85 57.78,79.85 59.37,81.44 64.14,81.44 65.41,80.17
SDO
  Bottom 0.813: IC1.26 59.69,62.07 R5.2
VCC  (via drill 0.8 pad 1.42)
  Top 0.406: v49.53,50.64 v63.5,50.64
  Bottom 0.305: 20.32,17.62 20.32,20.16 | 27.94,15.08 27.94,17.62 | 27.94,17.94 27.94,20.16
  Bottom 0.406: IC1.11 v49.53,50.64 | 63.5,55.09 63.5,58.9 | 21.75,30.48 21.75,30.64 R2.2
  Bottom 0.813: 20.32,17.62 KB1.14 21.59,13.81 24.13,11.27 27.94,11.27 | IC1.32 44.45,54.45 46.99,51.91 48.26,51.91 v49.53,50.64 IC1.11 49.53,39.21 | v63.5,50.64 63.5,55.09 | 63.5,58.9 64.45,59.85 66.36,59.85 70.48,63.98 70.48,64.93 | 70.48,64.93 IC2.3 | 20.32,20.16 20.32,29.05 21.75,30.48 24.13,32.86 R1.1 RN2.1 | 27.94,11.27 27.94,15.08 | 49.53,39.21 C5.1 | 27.94,11.27 81.28,11.27 82.55,12.54 LCD.2 91.76,25.56 91.76,43.97 P1.E | 49.53,39.21 43.81,39.21 33.66,29.05 33.66,26.51 27.94,20.8 27.94,20.16 | 70.48,64.93 D1.A | 27.94,17.62 27.94,17.94
(copper drawn outside any net)
  shapes: Bottom circle x2

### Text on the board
Top: IPL5X | http://www.5xproject.co.nr/ | V2.0 | 05/2010
Bottom: 05/2010 | V2.0 | http://www.5xproject.co.nr/ | IPL5X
